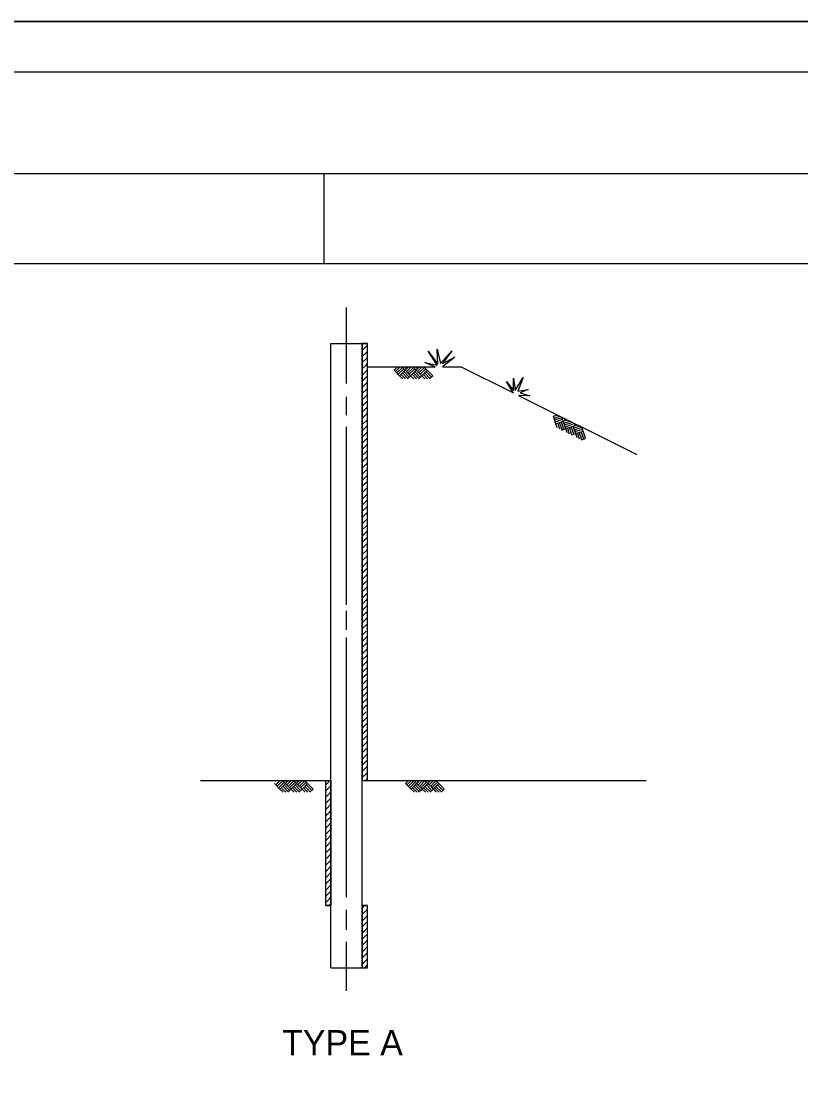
# Model space of a CAD drawing. Extents: x -0.04 to 2.79, y -0.02 to 1.81.
# Drawn here: x 1.4336 to 1.7532, y 1.3708 to 1.8125 of the extents above; entities that cross this region are included whole.
import ezdxf

# ---------------------------------------------------------------- set-up
doc = ezdxf.new("R2010")
doc.units = 0
for name, color, linetype in [('G-ANNO-NPLT', 7, 'Continuous'), ('G-ANNO-PLOT', 7, 'Continuous'), ('G-ANNO-TTLB', 7, 'Continuous'), ('Level 1', 7, 'Continuous')]:
    doc.layers.add(name, color=color, linetype=linetype)

msp = doc.modelspace()

# ---------------------------------------------------------------- linework, layer by layer
at = {"layer": 'G-ANNO-NPLT'}
msp.add_lwpolyline([(-0.04167, 1.8125), (2.79167, 1.8125), (2.79167, -0.02083), (-0.04167, -0.02083)], close=True, dxfattribs=at)
at = {"layer": 'G-ANNO-PLOT'}
msp.add_line((2.79167, 1.8125), (-0.04167, 1.8125), dxfattribs=at)
msp.add_lwpolyline([(0, 0), (2.79167, 0), (2.79167, 1.79167), (0, 1.79167)], close=True, dxfattribs=at)
at = {"layer": 'G-ANNO-TTLB'}
msp.add_line((1.55784, 1.71305), (1.55784, 1.75), dxfattribs=at)
for points in [[(0.08333, 0.04167), (2.72917, 0.04167), (2.72917, 1.75), (0.2515, 1.75)], [(0.11656, 0.08028), (2.69501, 0.08028), (2.69501, 1.71305), (0.11656, 1.71305)]]:
    msp.add_lwpolyline(points, dxfattribs=at)
at = {"layer": 'Level 1'}
for p, q in [((1.56695, 1.66393), (1.56695, 1.6951)), ((1.56052, 1.42402), (1.56052, 1.68033)), ((1.56052, 1.68033), (1.57556, 1.68033)), ((1.57337, 1.42402), (1.57337, 1.68033)), ((1.57556, 1.67076), (1.60338, 1.67076)), ((1.58649, 1.66933), (1.58772, 1.67056)), ((1.58704, 1.66878), (1.58882, 1.67056)), ((1.58766, 1.66823), (1.58991, 1.67049)), ((1.5882, 1.66769), (1.59046, 1.66994)), ((1.591, 1.66933), (1.58977, 1.67056)), ((1.59162, 1.66994), (1.59094, 1.67056)), ((1.591, 1.66933), (1.59224, 1.67056)), ((1.591, 1.66933), (1.59224, 1.67056)), ((1.59162, 1.66878), (1.5934, 1.67056)), ((1.59217, 1.67049), (1.5921, 1.67056)), ((1.59217, 1.66823), (1.59442, 1.67049)), ((1.59271, 1.66769), (1.59497, 1.66994)), ((1.59558, 1.66933), (1.59435, 1.67056)), ((1.59613, 1.66994), (1.59545, 1.67056)), ((1.59558, 1.66933), (1.59675, 1.67056)), ((1.59558, 1.66933), (1.59675, 1.67056)), ((1.59613, 1.66878), (1.59791, 1.67056)), ((1.59668, 1.67049), (1.59661, 1.67056)), ((1.59668, 1.66823), (1.59893, 1.67049)), ((1.59722, 1.66769), (1.59955, 1.66994)), ((1.6001, 1.66933), (1.59887, 1.67056)), ((1.60638, 1.67076), (1.61397, 1.67076)), ((1.61397, 1.67076), (1.6355, 1.66003)), ((1.58875, 1.66707), (1.58649, 1.66933)), ((1.58875, 1.66707), (1.591, 1.66933)), ((1.59005, 1.66577), (1.58875, 1.66707)), ((1.59121, 1.66577), (1.5893, 1.66769)), ((1.59217, 1.66598), (1.58991, 1.66823)), ((1.59271, 1.66652), (1.59046, 1.66878)), ((1.59326, 1.66707), (1.591, 1.66933)), ((1.59196, 1.66577), (1.59326, 1.66707)), ((1.59326, 1.66707), (1.59558, 1.66933)), ((1.59463, 1.66577), (1.59326, 1.66707)), ((1.59572, 1.66577), (1.59388, 1.66769)), ((1.59668, 1.66598), (1.59442, 1.66823)), ((1.59722, 1.66652), (1.59497, 1.66878)), ((1.59914, 1.66577), (1.59558, 1.66933)), ((1.59654, 1.66577), (1.59784, 1.66707)), ((1.59784, 1.66707), (1.6001, 1.66933)), ((1.60023, 1.66577), (1.59839, 1.66769)), ((1.60119, 1.66598), (1.59893, 1.66823)), ((1.6018, 1.66652), (1.59955, 1.66878)), ((1.60235, 1.66707), (1.6001, 1.66933)), ((1.60105, 1.66577), (1.60235, 1.66707)), ((1.56695, 1.65087), (1.56695, 1.65839)), ((1.63748, 1.65901), (1.68601, 1.63474)), ((1.65184, 1.65046), (1.65348, 1.65101)), ((1.65286, 1.64739), (1.65184, 1.65046)), ((1.65211, 1.64971), (1.65443, 1.65053)), ((1.65232, 1.64896), (1.65539, 1.64998)), ((1.65259, 1.64821), (1.6556, 1.64923)), ((1.65286, 1.64739), (1.65587, 1.64841)), ((1.65341, 1.64568), (1.65286, 1.64739)), ((1.65443, 1.6452), (1.65361, 1.64773)), ((1.65539, 1.64493), (1.65437, 1.64793)), ((1.65614, 1.64513), (1.65512, 1.64821)), ((1.65587, 1.64841), (1.65532, 1.65005)), ((1.65587, 1.64841), (1.65751, 1.64896)), ((1.65587, 1.64841), (1.65751, 1.64896)), ((1.65689, 1.6454), (1.65587, 1.64841)), ((1.65614, 1.64766), (1.65854, 1.64848)), ((1.65662, 1.64868), (1.65635, 1.64957)), ((1.65635, 1.64691), (1.65942, 1.64793)), ((1.65737, 1.64896), (1.65737, 1.64903)), ((1.66065, 1.6467), (1.66038, 1.64752)), ((1.56695, 1.57309), (1.56695, 1.64616)), ((1.65512, 1.64479), (1.65689, 1.6454)), ((1.65662, 1.64616), (1.6597, 1.64718)), ((1.65689, 1.6454), (1.65997, 1.64643)), ((1.65751, 1.64363), (1.65689, 1.6454)), ((1.65847, 1.64315), (1.65765, 1.64568)), ((1.65942, 1.64288), (1.6584, 1.64588)), ((1.66018, 1.64315), (1.65915, 1.64616)), ((1.65922, 1.64281), (1.66093, 1.64335)), ((1.65997, 1.64643), (1.66154, 1.64698)), ((1.65997, 1.64643), (1.66154, 1.64698)), ((1.66154, 1.64164), (1.65997, 1.64643)), ((1.66018, 1.64568), (1.66257, 1.64643)), ((1.66045, 1.64486), (1.66346, 1.64595)), ((1.66065, 1.64417), (1.66373, 1.64513)), ((1.66093, 1.64335), (1.664, 1.64438)), ((1.66147, 1.64691), (1.66141, 1.64704)), ((1.66257, 1.6411), (1.66168, 1.64363)), ((1.66346, 1.64082), (1.66243, 1.6439)), ((1.66428, 1.6411), (1.66325, 1.64411)), ((1.664, 1.64438), (1.66346, 1.64602)), ((1.66496, 1.64137), (1.664, 1.64438)), ((1.66325, 1.64076), (1.66496, 1.64137)), ((1.56695, 1.56277), (1.56695, 1.57063)), ((1.56695, 1.45306), (1.56695, 1.55962)), ((1.507, 1.50091), (1.56052, 1.50091)), ((1.5396, 1.49742), (1.53735, 1.49968)), ((1.5379, 1.49913), (1.53967, 1.50091)), ((1.53844, 1.49859), (1.54077, 1.50084)), ((1.53906, 1.49797), (1.54131, 1.50023)), ((1.5396, 1.49742), (1.54186, 1.49968)), ((1.5409, 1.49613), (1.5396, 1.49742)), ((1.54207, 1.49613), (1.54015, 1.49797)), ((1.54186, 1.49968), (1.54063, 1.50091)), ((1.54302, 1.49626), (1.54077, 1.49859)), ((1.54357, 1.49688), (1.54131, 1.49913)), ((1.54241, 1.50023), (1.54179, 1.50091)), ((1.54186, 1.49968), (1.54309, 1.50091)), ((1.54186, 1.49968), (1.54309, 1.50091)), ((1.54412, 1.49742), (1.54186, 1.49968)), ((1.54241, 1.49913), (1.54425, 1.50091)), ((1.54282, 1.49613), (1.54412, 1.49742)), ((1.54302, 1.50084), (1.54295, 1.50091)), ((1.54302, 1.49852), (1.54528, 1.50084)), ((1.54357, 1.49797), (1.54582, 1.50023)), ((1.54412, 1.49742), (1.54637, 1.49968)), ((1.54541, 1.49613), (1.54412, 1.49742)), ((1.54658, 1.49613), (1.54473, 1.49797)), ((1.54637, 1.49968), (1.54521, 1.50091)), ((1.54753, 1.49626), (1.54528, 1.49852)), ((1.54808, 1.49688), (1.54582, 1.49913)), ((1.54699, 1.50023), (1.5463, 1.50091)), ((1.54637, 1.49968), (1.5476, 1.50091)), ((1.54637, 1.49968), (1.5476, 1.50091)), ((1.54999, 1.49613), (1.54637, 1.49968)), ((1.54699, 1.49913), (1.54876, 1.50091)), ((1.54733, 1.49613), (1.5487, 1.49742)), ((1.54753, 1.50084), (1.54747, 1.50091)), ((1.54753, 1.49852), (1.54979, 1.50084)), ((1.54808, 1.49797), (1.55034, 1.50023)), ((1.5487, 1.49742), (1.55095, 1.49968)), ((1.55109, 1.49613), (1.54924, 1.49797)), ((1.55095, 1.49968), (1.54972, 1.50091)), ((1.55204, 1.49626), (1.54979, 1.49852)), ((1.55266, 1.49688), (1.55034, 1.49913)), ((1.55321, 1.49742), (1.55095, 1.49968)), ((1.55191, 1.49613), (1.55321, 1.49742)), ((1.5584, 1.44965), (1.5584, 1.50091)), ((1.57317, 1.50091), (1.68991, 1.50091)), ((1.59121, 1.49968), (1.59244, 1.50091)), ((1.59347, 1.49742), (1.59121, 1.49968)), ((1.59176, 1.49913), (1.5936, 1.50091)), ((1.59237, 1.49859), (1.59463, 1.50084)), ((1.59292, 1.49797), (1.59517, 1.50023)), ((1.59347, 1.49742), (1.59572, 1.49968)), ((1.59483, 1.49613), (1.59347, 1.49742)), ((1.59593, 1.49613), (1.59408, 1.49797)), ((1.59579, 1.49968), (1.59456, 1.50091)), ((1.59688, 1.49626), (1.59463, 1.49859)), ((1.59743, 1.49688), (1.59517, 1.49913)), ((1.59634, 1.50023), (1.59565, 1.50091)), ((1.59804, 1.49742), (1.59572, 1.49968)), ((1.59579, 1.49968), (1.59695, 1.50091)), ((1.59579, 1.49968), (1.59695, 1.50091)), ((1.59634, 1.49913), (1.59811, 1.50091)), ((1.59668, 1.49613), (1.59804, 1.49742)), ((1.59688, 1.50084), (1.59681, 1.50091)), ((1.59688, 1.49852), (1.59914, 1.50084)), ((1.59743, 1.49797), (1.59975, 1.50023)), ((1.59804, 1.49742), (1.6003, 1.49968)), ((1.59934, 1.49613), (1.59804, 1.49742)), ((1.60044, 1.49613), (1.59859, 1.49797)), ((1.6003, 1.49968), (1.59907, 1.50091)), ((1.60139, 1.49626), (1.59914, 1.49852)), ((1.60201, 1.49688), (1.59975, 1.49913)), ((1.60085, 1.50023), (1.60023, 1.50091)), ((1.6003, 1.49968), (1.60153, 1.50091)), ((1.6003, 1.49968), (1.60153, 1.50091)), ((1.60385, 1.49613), (1.6003, 1.49968)), ((1.60085, 1.49913), (1.60262, 1.50091)), ((1.60126, 1.49613), (1.60256, 1.49742)), ((1.60139, 1.50084), (1.60133, 1.50091)), ((1.60139, 1.49852), (1.60365, 1.50084)), ((1.60201, 1.49797), (1.60426, 1.50023)), ((1.60256, 1.49742), (1.60481, 1.49968)), ((1.60502, 1.49613), (1.6031, 1.49797)), ((1.60481, 1.49968), (1.60358, 1.50091)), ((1.60597, 1.49626), (1.60365, 1.49852)), ((1.60652, 1.49688), (1.60426, 1.49913)), ((1.60707, 1.49742), (1.60481, 1.49968)), ((1.60577, 1.49613), (1.60707, 1.49742)), ((1.5584, 1.44965), (1.56052, 1.44965)), ((1.57344, 1.44965), (1.57556, 1.44965)), ((1.57556, 1.42402), (1.57556, 1.44965)), ((1.56695, 1.43967), (1.56695, 1.44794)), ((1.56695, 1.41458), (1.56695, 1.43475)), ((1.56052, 1.42402), (1.57556, 1.42402))]:
    msp.add_line(p, q, dxfattribs=at)
for points in [[(1.57556, 1.50091), (1.57556, 1.68033), (1.57337, 1.68033), (1.57337, 1.50091)], [(1.5584, 1.44965), (1.5584, 1.50091), (1.56052, 1.50091), (1.56052, 1.44965)], [(1.57556, 1.42402), (1.57556, 1.44965), (1.57344, 1.44965), (1.57344, 1.42402)]]:
    msp.add_lwpolyline(points, close=True, dxfattribs=at)
for points in [[(1.57337, 1.68006), (1.57371, 1.68033)], [(1.57337, 1.67753), (1.57501, 1.67917)], [(1.57501, 1.67917), (1.57556, 1.67965)], [(1.57337, 1.675), (1.57501, 1.67657)], [(1.57337, 1.67247), (1.57501, 1.67404)], [(1.57501, 1.67657), (1.57556, 1.67712)], [(1.57501, 1.67404), (1.57556, 1.67459)], [(1.60351, 1.67056), (1.59907, 1.67254), (1.6042, 1.67145), (1.60044, 1.67719), (1.6044, 1.67186)], [(1.6044, 1.67186), (1.6042, 1.67801), (1.6055, 1.67206), (1.61014, 1.67739), (1.60638, 1.67206), (1.61144, 1.67473), (1.60638, 1.67076)], [(1.57337, 1.66987), (1.57501, 1.67151)], [(1.57501, 1.67151), (1.57556, 1.67206)], [(1.57501, 1.66899), (1.57556, 1.66946)], [(1.57337, 1.66734), (1.57501, 1.66899)], [(1.57337, 1.66482), (1.57501, 1.66646)], [(1.57501, 1.66646), (1.57556, 1.66693)], [(1.6353, 1.6601), (1.63263, 1.66475), (1.6355, 1.66099), (1.6355, 1.66605), (1.63618, 1.66099), (1.63947, 1.66632), (1.63728, 1.66078), (1.64152, 1.6614), (1.63817, 1.6601), (1.64213, 1.6588), (1.63748, 1.65901)], [(1.57337, 1.66229), (1.57501, 1.66393)], [(1.57337, 1.65976), (1.57501, 1.66133)], [(1.57501, 1.66393), (1.57556, 1.66441)], [(1.57501, 1.66133), (1.57556, 1.66188)], [(1.57337, 1.65716), (1.57501, 1.6588)], [(1.57337, 1.65463), (1.57501, 1.65627)], [(1.57501, 1.6588), (1.57556, 1.65935)], [(1.57501, 1.65627), (1.57556, 1.65682)], [(1.57337, 1.6521), (1.57501, 1.65374)], [(1.57501, 1.65374), (1.57556, 1.65422)], [(1.57337, 1.64957), (1.57501, 1.65121)], [(1.57337, 1.64704), (1.57501, 1.64862)], [(1.57501, 1.65121), (1.57556, 1.65169)], [(1.57501, 1.64862), (1.57556, 1.64916)], [(1.57337, 1.64452), (1.57501, 1.64609)], [(1.57337, 1.64192), (1.57501, 1.64356)], [(1.57501, 1.64609), (1.57556, 1.64663)], [(1.57501, 1.64356), (1.57556, 1.64411)], [(1.57337, 1.63939), (1.57501, 1.64103)], [(1.57501, 1.64103), (1.57556, 1.64151)], [(1.57501, 1.6385), (1.57556, 1.63898)], [(1.57337, 1.63686), (1.57501, 1.6385)], [(1.57337, 1.63433), (1.57501, 1.6359)], [(1.57501, 1.6359), (1.57556, 1.63645)], [(1.57337, 1.6318), (1.57501, 1.63337)], [(1.57337, 1.6292), (1.57501, 1.63085)], [(1.57501, 1.63337), (1.57556, 1.63392)], [(1.57501, 1.63085), (1.57556, 1.63139)], [(1.57337, 1.62668), (1.57501, 1.62832)], [(1.57337, 1.62415), (1.57501, 1.62579)], [(1.57501, 1.62832), (1.57556, 1.62879)], [(1.57501, 1.62579), (1.57556, 1.62627)], [(1.57337, 1.62162), (1.57501, 1.62326)], [(1.57501, 1.62326), (1.57556, 1.62374)], [(1.57501, 1.62066), (1.57556, 1.62121)], [(1.57337, 1.61909), (1.57501, 1.62066)], [(1.57337, 1.61649), (1.57501, 1.61813)], [(1.57501, 1.61813), (1.57556, 1.61868)], [(1.57337, 1.61396), (1.57501, 1.6156)], [(1.57337, 1.61143), (1.57501, 1.61307)], [(1.57501, 1.6156), (1.57556, 1.61615)], [(1.57501, 1.61307), (1.57556, 1.61355)], [(1.57337, 1.6089), (1.57501, 1.61055)], [(1.57337, 1.60638), (1.57501, 1.60795)], [(1.57501, 1.61055), (1.57556, 1.61102)], [(1.57501, 1.60795), (1.57556, 1.60849)], [(1.57337, 1.60385), (1.57501, 1.60542)], [(1.57501, 1.60542), (1.57556, 1.60597)], [(1.57501, 1.60289), (1.57556, 1.60344)], [(1.57337, 1.60125), (1.57501, 1.60289)], [(1.57337, 1.59872), (1.57501, 1.60036)], [(1.57501, 1.60036), (1.57556, 1.60084)], [(1.57337, 1.59619), (1.57501, 1.59783)], [(1.57337, 1.59366), (1.57501, 1.59523)], [(1.57501, 1.59783), (1.57556, 1.59831)], [(1.57501, 1.59523), (1.57556, 1.59578)], [(1.57337, 1.59113), (1.57501, 1.59271)], [(1.57337, 1.58854), (1.57501, 1.59018)], [(1.57501, 1.59271), (1.57556, 1.59325)], [(1.57501, 1.59018), (1.57556, 1.59072)], [(1.57337, 1.58601), (1.57501, 1.58765)], [(1.57501, 1.58765), (1.57556, 1.58813)], [(1.57501, 1.58512), (1.57556, 1.5856)], [(1.57337, 1.58348), (1.57501, 1.58512)], [(1.57337, 1.58095), (1.57501, 1.58259)], [(1.57501, 1.58259), (1.57556, 1.58307)], [(1.57337, 1.57842), (1.57501, 1.57999)], [(1.57337, 1.57582), (1.57501, 1.57746)], [(1.57501, 1.57999), (1.57556, 1.58054)], [(1.57501, 1.57746), (1.57556, 1.57801)], [(1.57337, 1.57329), (1.57501, 1.57493)], [(1.57337, 1.57076), (1.57501, 1.57241)], [(1.57501, 1.57493), (1.57556, 1.57548)], [(1.57501, 1.57241), (1.57556, 1.57288)], [(1.57337, 1.56824), (1.57501, 1.56988)], [(1.57501, 1.56988), (1.57556, 1.57035)], [(1.57337, 1.56571), (1.57501, 1.56728)], [(1.57337, 1.56318), (1.57501, 1.56475)], [(1.57501, 1.56728), (1.57556, 1.56783)], [(1.57501, 1.56475), (1.57556, 1.5653)], [(1.57337, 1.56058), (1.57501, 1.56222)], [(1.57337, 1.55805), (1.57501, 1.55969)], [(1.57501, 1.55969), (1.57556, 1.56017)], [(1.57337, 1.55552), (1.57501, 1.55716)], [(1.57501, 1.55716), (1.57556, 1.55764)], [(1.57501, 1.55457), (1.57556, 1.55511)], [(1.57337, 1.55299), (1.57501, 1.55457)], [(1.57337, 1.55046), (1.57501, 1.55204)], [(1.57501, 1.55204), (1.57556, 1.55258)], [(1.57337, 1.54787), (1.57501, 1.54951)], [(1.57337, 1.54534), (1.57501, 1.54698)], [(1.57501, 1.54951), (1.57556, 1.55005)], [(1.57501, 1.54698), (1.57556, 1.54746)], [(1.57337, 1.54281), (1.57501, 1.54445)], [(1.57337, 1.54028), (1.57501, 1.54192)], [(1.57501, 1.54445), (1.57556, 1.54493)], [(1.57501, 1.54192), (1.57556, 1.5424)], [(1.57337, 1.53775), (1.57501, 1.53932)], [(1.57501, 1.53932), (1.57556, 1.53987)], [(1.57501, 1.53679), (1.57556, 1.53734)], [(1.57337, 1.53515), (1.57501, 1.53679)], [(1.57337, 1.53263), (1.57501, 1.53427)], [(1.57501, 1.53427), (1.57556, 1.53481)], [(1.57337, 1.5301), (1.57501, 1.53174)], [(1.57337, 1.52757), (1.57501, 1.52921)], [(1.57501, 1.53174), (1.57556, 1.53222)], [(1.57337, 1.52497), (1.57501, 1.52661)], [(1.57337, 1.52244), (1.57501, 1.52408)], [(1.57501, 1.52661), (1.57556, 1.52716)], [(1.57501, 1.52408), (1.57556, 1.52456)], [(1.57337, 1.51991), (1.57501, 1.52155)], [(1.57501, 1.52155), (1.57556, 1.52203)], [(1.57501, 1.51896), (1.57556, 1.5195)], [(1.57337, 1.51738), (1.57501, 1.51896)], [(1.57337, 1.51479), (1.57501, 1.51643)], [(1.57501, 1.51643), (1.57556, 1.51697)], [(1.57337, 1.51226), (1.57501, 1.5139)], [(1.57337, 1.50973), (1.57501, 1.51137)], [(1.57501, 1.5139), (1.57556, 1.51444)], [(1.57501, 1.51137), (1.57556, 1.51185)], [(1.57337, 1.5072), (1.57501, 1.50884)], [(1.57337, 1.50467), (1.57501, 1.50624)], [(1.57501, 1.50884), (1.57556, 1.50932)], [(1.57501, 1.50624), (1.57556, 1.50679)], [(1.57337, 1.50214), (1.57501, 1.50371)], [(1.57501, 1.50371), (1.57556, 1.50426)], [(1.57501, 1.50118), (1.57556, 1.50173)], [(1.5584, 1.4992), (1.55895, 1.49975)], [(1.5584, 1.49667), (1.55895, 1.49722)], [(1.55895, 1.49975), (1.56011, 1.50091)], [(1.55895, 1.49722), (1.56052, 1.49879)], [(1.57474, 1.50091), (1.57501, 1.50118)], [(1.5584, 1.49414), (1.55895, 1.49469)], [(1.55895, 1.49469), (1.56052, 1.49626)], [(1.55895, 1.49216), (1.56052, 1.49373)], [(1.5584, 1.49161), (1.55895, 1.49216)], [(1.5584, 1.48909), (1.55895, 1.48956)], [(1.55895, 1.48956), (1.56052, 1.4912)], [(1.55895, 1.48704), (1.56052, 1.48861)], [(1.5584, 1.48649), (1.55895, 1.48704)], [(1.5584, 1.48396), (1.55895, 1.48451)], [(1.55895, 1.48451), (1.56052, 1.48608)], [(1.5584, 1.48143), (1.55895, 1.48198)], [(1.55895, 1.48198), (1.56052, 1.48355)], [(1.55895, 1.47945), (1.56052, 1.48102)], [(1.5584, 1.4789), (1.55895, 1.47945)], [(1.5584, 1.47637), (1.55895, 1.47685)], [(1.55895, 1.47685), (1.56052, 1.47849)], [(1.55895, 1.47432), (1.56052, 1.47589)], [(1.5584, 1.47378), (1.55895, 1.47432)], [(1.5584, 1.47125), (1.55895, 1.47179)], [(1.55895, 1.47179), (1.56052, 1.47337)], [(1.55895, 1.46926), (1.56052, 1.47084)], [(1.5584, 1.46872), (1.55895, 1.46926)], [(1.5584, 1.46619), (1.55895, 1.46674)], [(1.55895, 1.46674), (1.56052, 1.46831)], [(1.5584, 1.46366), (1.55895, 1.46414)], [(1.55895, 1.46414), (1.56052, 1.46578)], [(1.55895, 1.46161), (1.56052, 1.46318)], [(1.5584, 1.46106), (1.55895, 1.46161)], [(1.5584, 1.45853), (1.55895, 1.45908)], [(1.55895, 1.45908), (1.56052, 1.46065)], [(1.55895, 1.45655), (1.56052, 1.45812)], [(1.5584, 1.456), (1.55895, 1.45655)], [(1.5584, 1.45347), (1.55895, 1.45402)], [(1.55895, 1.45402), (1.56052, 1.45559)], [(1.55895, 1.45149), (1.56052, 1.45306)], [(1.5584, 1.45095), (1.55895, 1.45149)], [(1.55963, 1.44965), (1.56052, 1.45054)], [(1.57344, 1.44849), (1.57419, 1.44931)], [(1.57419, 1.44931), (1.57453, 1.44965)], [(1.57344, 1.44596), (1.57419, 1.44678)], [(1.57419, 1.44678), (1.57556, 1.44808)], [(1.57419, 1.44418), (1.57556, 1.44555)], [(1.57344, 1.44343), (1.57419, 1.44418)], [(1.57344, 1.4409), (1.57419, 1.44165)], [(1.57419, 1.44165), (1.57556, 1.44302)], [(1.57419, 1.43912), (1.57556, 1.44049)], [(1.57344, 1.43837), (1.57419, 1.43912)], [(1.57344, 1.43577), (1.57419, 1.43659)], [(1.57419, 1.43659), (1.57556, 1.43789)], [(1.57344, 1.43324), (1.57419, 1.43406)], [(1.57344, 1.43071), (1.57419, 1.43147)], [(1.57419, 1.43406), (1.57556, 1.43536)], [(1.57419, 1.43147), (1.57556, 1.43283)], [(1.57344, 1.42819), (1.57419, 1.42894)], [(1.57419, 1.42894), (1.57556, 1.4303)], [(1.57419, 1.42641), (1.57556, 1.42778)], [(1.57344, 1.42566), (1.57419, 1.42641)], [(1.57433, 1.42402), (1.57556, 1.42525)]]:
    msp.add_lwpolyline(points, dxfattribs=at)

# ---------------------------------------------------------------- texts
msp.add_text('TYPE A', height=0.010417).set_placement((1.54053, 1.38813))

doc.saveas('drawing.dxf')
